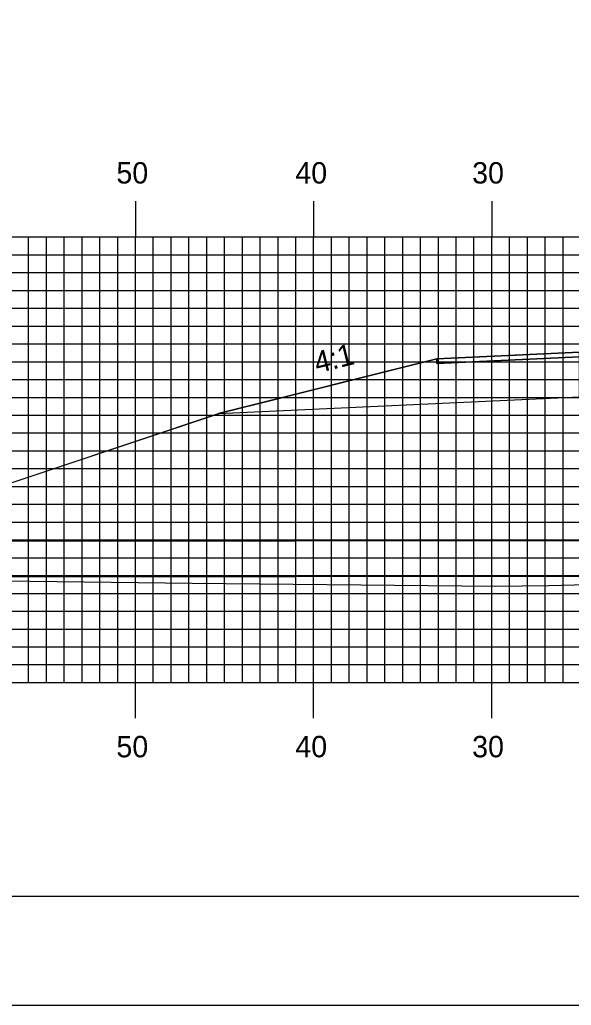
# Model space of a CAD drawing. Extents: x 1757462 to 1757806, y 442591 to 442811.
# Drawn here: x 1757571.6 to 1757602.6, y 442590.5 to 442645.9 of the extents above; entities that cross this region are included whole.
import ezdxf

# ---------------------------------------------------------------- set-up
doc = ezdxf.new("R2010")
doc.units = 0
for name, color, linetype in [('ANNOTATION', 7, 'Continuous'), ('BORDER', 7, 'Continuous'), ('D_Drainage_Culvert', 7, 'Continuous'), ('D_Roadway_Centerline', 7, 'Continuous'), ('D_Roadway_Edge_Shoulder', 7, 'Continuous'), ('D_Roadway_SlopeLines', 7, 'Continuous'), ('D_Roadway_SubGrade', 7, 'Continuous'), ('H_V ANNOTATION', 7, 'Continuous'), ('MAJOR', 7, 'Continuous'), ('MINOR', 7, 'Continuous'), ('PLOT BOUNDARY', 7, 'Continuous'), ('S_Roadway_Centerline', 7, 'Continuous')]:
    doc.layers.add(name, color=color, linetype=linetype)

msp = doc.modelspace()

# ---------------------------------------------------------------- linework, layer by layer
at = {"layer": 'BORDER'}
msp.add_lwpolyline([(1757478.509, 442596.665), (1757798.509, 442596.665), (1757798.509, 442806.665), (1757478.509, 442806.665)], close=True, dxfattribs=at)
at = {"layer": 'D_Drainage_Culvert'}
for p, q in [((1757686.109, 442616.715), (1757558.109, 442616.557)), ((1757686.109, 442614.715), (1757558.111, 442614.557))]:
    msp.add_line(p, q, dxfattribs=at)
at = {"layer": 'D_Roadway_Centerline'}
msp.add_lwpolyline([(1757558.111, 442614.557), (1757563.908, 442617.456), (1757582.764, 442623.757), (1757582.773, 442623.759), (1757583.02, 442623.821), (1757583.21, 442623.869), (1757583.604, 442623.967), (1757584.407, 442624.168), (1757584.513, 442624.194), (1757591.665, 442625.983), (1757595.028, 442626.824), (1757598.641, 442626.991), (1757603.034, 442627.194), (1757605.832, 442627.323), (1757615.739, 442627.78), (1757616.109, 442627.788), (1757628.109, 442628.028), (1757640.109, 442627.788), (1757648.109, 442627.468), (1757658.283, 442624.924), (1757660.109, 442624.468), (1757679.6, 442617.971)], dxfattribs=at)
at = {"layer": 'D_Roadway_Edge_Shoulder'}
msp.add_lwpolyline([(1757603.034, 442627.194), (1757595.028, 442626.824), (1757595.028, 442626.574), (1757603.034, 442626.944)], close=True, dxfattribs=at)
at = {"layer": 'D_Roadway_SlopeLines'}
msp.add_lwpolyline([(1757595.028, 442626.824), (1757583.02, 442623.821), (1757563.908, 442617.456)], dxfattribs=at)
at = {"layer": 'D_Roadway_SubGrade'}
msp.add_lwpolyline([(1757603.034, 442626.528), (1757603.034, 442626.944), (1757595.028, 442626.574), (1757595.028, 442626.824), (1757582.764, 442623.757), (1757603.034, 442624.694)], close=True, dxfattribs=at)
at = {"layer": 'MAJOR'}
for p, q in [((1757578.109, 442635.669), (1757578.109, 442633.665)), ((1757588.109, 442635.669), (1757588.109, 442633.665)), ((1757598.109, 442635.669), (1757598.109, 442633.665)), ((1757488.109, 442633.665), (1757768.109, 442633.665)), ((1757488.109, 442633.665), (1757768.109, 442633.665)), ((1757578.109, 442608.665), (1757578.109, 442633.665)), ((1757588.109, 442608.665), (1757588.109, 442633.665)), ((1757598.109, 442608.665), (1757598.109, 442633.665)), ((1757488.109, 442628.665), (1757768.109, 442628.665)), ((1757488.109, 442623.665), (1757768.109, 442623.665)), ((1757488.109, 442618.665), (1757768.109, 442618.665)), ((1757488.109, 442613.665), (1757768.109, 442613.665)), ((1757488.109, 442608.665), (1757768.109, 442608.665)), ((1757488.109, 442608.665), (1757768.109, 442608.665)), ((1757578.109, 442606.661), (1757578.109, 442608.665)), ((1757588.109, 442606.661), (1757588.109, 442608.665)), ((1757598.109, 442606.661), (1757598.109, 442608.665))]:
    msp.add_line(p, q, dxfattribs=at)
at = {"layer": 'MINOR'}
for p, q in [((1757572.109, 442608.665), (1757572.109, 442633.665)), ((1757573.109, 442608.665), (1757573.109, 442633.665)), ((1757574.109, 442608.665), (1757574.109, 442633.665)), ((1757575.109, 442608.665), (1757575.109, 442633.665)), ((1757576.109, 442608.665), (1757576.109, 442633.665)), ((1757577.109, 442608.665), (1757577.109, 442633.665)), ((1757579.109, 442608.665), (1757579.109, 442633.665)), ((1757580.109, 442608.665), (1757580.109, 442633.665)), ((1757581.109, 442608.665), (1757581.109, 442633.665)), ((1757582.109, 442608.665), (1757582.109, 442633.665)), ((1757583.109, 442608.665), (1757583.109, 442633.665)), ((1757584.109, 442608.665), (1757584.109, 442633.665)), ((1757585.109, 442608.665), (1757585.109, 442633.665)), ((1757586.109, 442608.665), (1757586.109, 442633.665)), ((1757587.109, 442608.665), (1757587.109, 442633.665)), ((1757589.109, 442608.665), (1757589.109, 442633.665)), ((1757590.109, 442608.665), (1757590.109, 442633.665)), ((1757591.109, 442608.665), (1757591.109, 442633.665)), ((1757592.109, 442608.665), (1757592.109, 442633.665)), ((1757593.109, 442608.665), (1757593.109, 442633.665)), ((1757594.109, 442608.665), (1757594.109, 442633.665)), ((1757595.109, 442608.665), (1757595.109, 442633.665)), ((1757596.109, 442608.665), (1757596.109, 442633.665)), ((1757597.109, 442608.665), (1757597.109, 442633.665)), ((1757599.109, 442608.665), (1757599.109, 442633.665)), ((1757600.109, 442608.665), (1757600.109, 442633.665)), ((1757601.109, 442608.665), (1757601.109, 442633.665)), ((1757602.109, 442608.665), (1757602.109, 442633.665)), ((1757488.109, 442632.665), (1757768.109, 442632.665)), ((1757488.109, 442631.665), (1757768.109, 442631.665)), ((1757488.109, 442630.665), (1757768.109, 442630.665)), ((1757488.109, 442629.665), (1757768.109, 442629.665)), ((1757488.109, 442627.665), (1757768.109, 442627.665)), ((1757488.109, 442626.665), (1757768.109, 442626.665)), ((1757488.109, 442625.665), (1757768.109, 442625.665)), ((1757488.109, 442624.665), (1757768.109, 442624.665)), ((1757488.109, 442622.665), (1757768.109, 442622.665)), ((1757488.109, 442621.665), (1757768.109, 442621.665)), ((1757488.109, 442620.665), (1757768.109, 442620.665)), ((1757488.109, 442619.665), (1757768.109, 442619.665)), ((1757488.109, 442617.665), (1757768.109, 442617.665)), ((1757488.109, 442616.665), (1757768.109, 442616.665)), ((1757488.109, 442615.665), (1757768.109, 442615.665)), ((1757488.109, 442614.665), (1757768.109, 442614.665)), ((1757488.109, 442612.665), (1757768.109, 442612.665)), ((1757488.109, 442611.665), (1757768.109, 442611.665)), ((1757488.109, 442610.665), (1757768.109, 442610.665)), ((1757488.109, 442609.665), (1757768.109, 442609.665))]:
    msp.add_line(p, q, dxfattribs=at)
at = {"layer": 'PLOT BOUNDARY'}
msp.add_lwpolyline([(1757462.322, 442590.547), (1757802.322, 442590.547), (1757802.322, 442810.547), (1757462.322, 442810.547)], close=True, dxfattribs=at)
at = {"layer": 'S_Roadway_Centerline'}
msp.add_lwpolyline([(1757488.109, 442613.681), (1757501.174, 442613.774), (1757507.938, 442613.713), (1757514.358, 442613.67), (1757553.808, 442614.566), (1757553.885, 442614.569), (1757553.999, 442614.568), (1757581.299, 442614.243), (1757598.308, 442614.069), (1757601.318, 442614.107), (1757627.786, 442614.802), (1757645.879, 442614.856), (1757665.066, 442614.914), (1757687.389, 442614.706), (1757688.629, 442614.724), (1757691.05, 442614.709), (1757726.032, 442615.161), (1757736.486, 442615.206), (1757747, 442615.3), (1757756.186, 442615.673), (1757758.953, 442615.741), (1757767.312, 442615.605), (1757768.109, 442615.604)], dxfattribs=at)

# ---------------------------------------------------------------- texts
at = {"layer": 'ANNOTATION'}
msp.add_text('4:1', height=1.2, rotation=14.0409, dxfattribs=at).set_placement((1757588.306, 442626.005))
at = {"layer": 'H_V ANNOTATION'}
for s, p in [('50', (1757577.038, 442636.665)), ('40', (1757587.081, 442636.665)), ('30', (1757597.006, 442636.665)), ('50', (1757577.038, 442604.465)), ('40', (1757587.081, 442604.465)), ('30', (1757597.006, 442604.465))]:
    msp.add_text(s, height=1.2, dxfattribs=at).set_placement(p)

doc.saveas('drawing.dxf')
